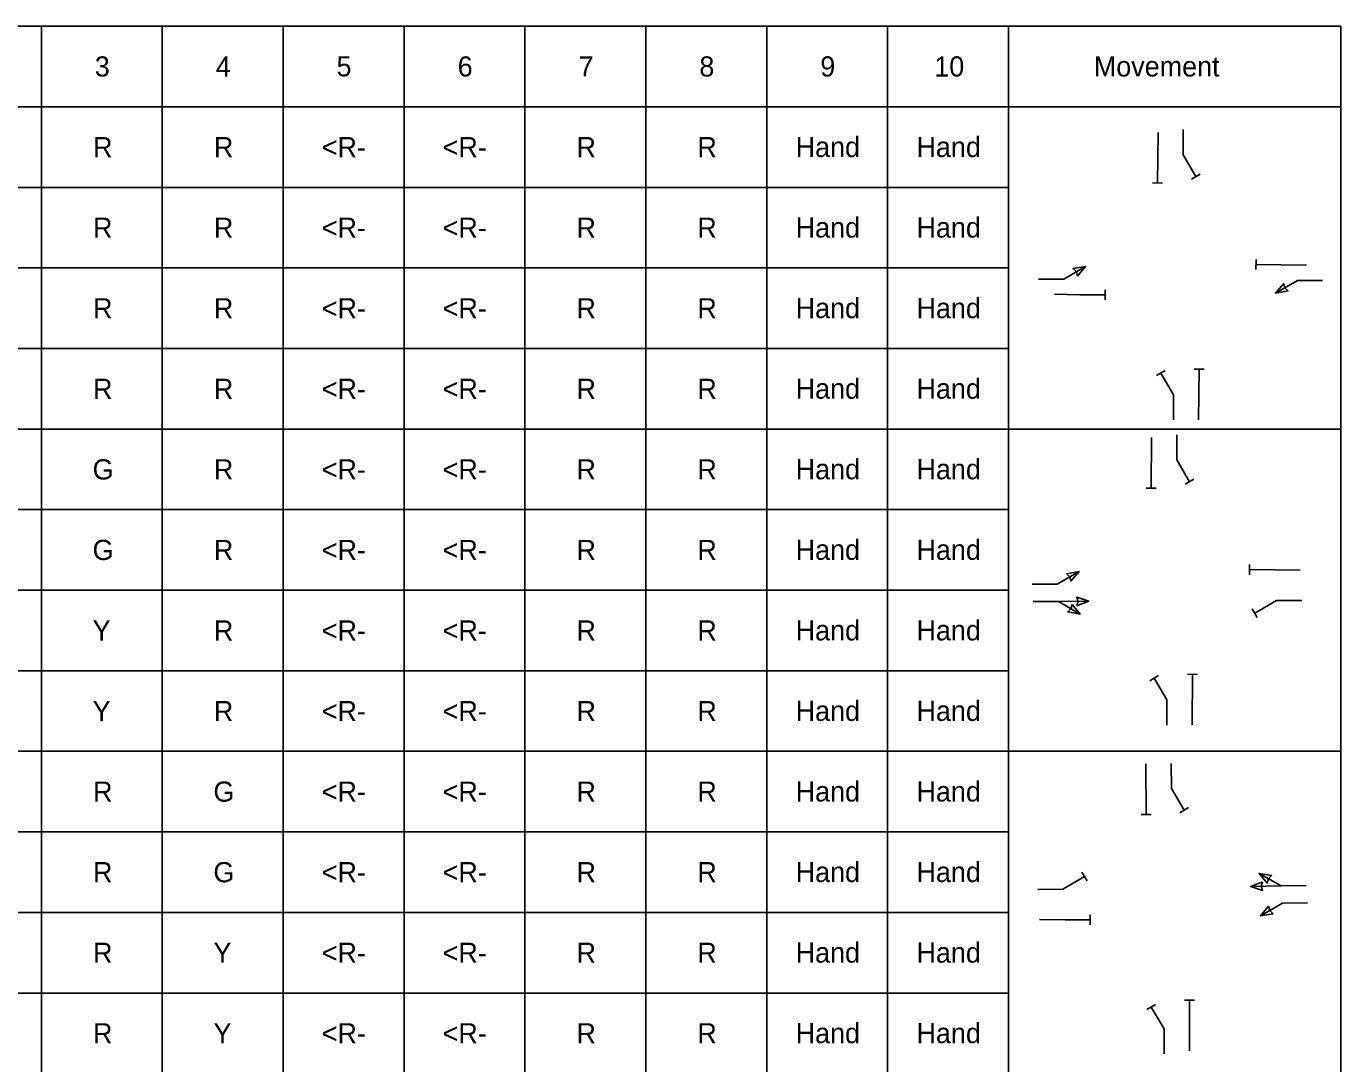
# Model space of a CAD drawing. Extents: x 515543 to 517243, y 660510 to 662861.
# Drawn here: x 515943.9 to 516385.7, y 660844.6 to 661193.4 of the extents above; entities that cross this region are included whole.
import ezdxf

# ---------------------------------------------------------------- set-up
doc = ezdxf.new("R2010")
doc.units = 0
doc.layers.add('Default', color=7, linetype='Continuous')

msp = doc.modelspace()

# ---------------------------------------------------------------- linework, layer by layer
at = {"layer": 'Default'}
for p, q in [((515695.04, 661193.38), (516385.67, 661193.38)), ((515948.98, 661193.38), (515948.98, 660597.54)), ((515989.6, 661193.38), (515989.6, 660597.54)), ((516030.23, 661193.38), (516030.23, 660597.54)), ((516070.85, 661193.38), (516070.85, 660597.54)), ((516111.48, 661193.38), (516111.48, 660597.54)), ((516152.1, 661193.38), (516152.1, 660597.54)), ((516192.73, 661193.38), (516192.73, 660597.54)), ((516233.35, 661193.38), (516233.35, 660597.54)), ((516273.98, 661193.38), (516273.98, 660597.54)), ((516385.67, 661193.38), (516385.67, 660597.54)), ((515695.04, 661166.29), (516385.67, 661166.29)), ((516324.26, 661157.72), (516324.12, 661140.69)), ((516332.77, 661158.65), (516332.77, 661150.18)), ((516332.77, 661150.18), (516337, 661142.85)), ((516322.43, 661140.7), (516325.81, 661140.67)), ((516338.47, 661143.7), (516335.54, 661142.01)), ((515776.29, 661139.21), (516273.98, 661139.21)), ((516357.2, 661114.98), (516357.17, 661111.6)), ((515776.29, 661112.13), (516273.98, 661112.13)), ((515948.98, 661112.13), (516273.98, 661112.13)), ((516292.57, 661108.4), (516299.9, 661112.63)), ((516299.9, 661112.63), (516295.73, 661111.9)), ((516296.82, 661110.86), (516295.73, 661111.9)), ((516297.18, 661109.39), (516296.82, 661110.86)), ((516299.9, 661112.63), (516297.18, 661109.39)), ((516365.65, 661113.22), (516357.18, 661113.29)), ((516374.22, 661113.06), (516365.65, 661113.22)), ((516284.1, 661108.4), (516292.57, 661108.4)), ((516306.48, 661101.36), (516306.51, 661104.74)), ((516371.11, 661107.94), (516363.78, 661103.71)), ((516363.78, 661103.71), (516366.5, 661106.95)), ((516366.5, 661106.95), (516366.86, 661105.48)), ((516366.86, 661105.48), (516367.95, 661104.44)), ((516379.57, 661107.94), (516371.11, 661107.94)), ((516289.45, 661103.28), (516298.03, 661103.12)), ((516298.03, 661103.12), (516306.49, 661103.05)), ((516363.78, 661103.71), (516367.95, 661104.44)), ((515776.29, 661085.04), (516273.98, 661085.04)), ((516339.75, 661078.09), (516336.37, 661078.12)), ((516337.92, 661061.07), (516338.06, 661078.11)), ((516323.71, 661075.96), (516326.64, 661077.66)), ((516329.41, 661069.48), (516325.18, 661076.81)), ((516329.41, 661061.02), (516329.41, 661069.48)), ((515695.04, 661057.96), (516385.67, 661057.96)), ((516192.73, 661057.96), (516233.35, 661057.96)), ((516233.35, 661057.96), (516273.98, 661057.96)), ((516330.59, 661056.06), (516330.59, 661047.6)), ((516322.08, 661055.14), (516321.94, 661038.1)), ((516330.59, 661047.6), (516334.82, 661040.27)), ((516336.29, 661041.11), (516333.35, 661039.42)), ((516320.25, 661038.11), (516323.63, 661038.08)), ((515776.29, 661030.88), (516273.98, 661030.88)), ((516355.02, 661012.4), (516354.99, 661009.01)), ((516290.38, 661005.81), (516297.71, 661010.05)), ((516297.71, 661010.05), (516293.55, 661009.31)), ((516294.64, 661008.27), (516293.55, 661009.31)), ((516294.99, 661006.8), (516294.64, 661008.27)), ((516297.71, 661010.05), (516294.99, 661006.8)), ((516363.47, 661010.64), (516355, 661010.7)), ((516372.04, 661010.48), (516363.47, 661010.64)), ((515776.29, 661003.79), (516273.98, 661003.79)), ((515948.98, 661003.79), (516273.98, 661003.79)), ((516281.92, 661005.81), (516290.38, 661005.81)), ((516282.29, 660999.98), (516290.76, 660999.98)), ((516282.29, 660999.98), (516290.76, 660999.98)), ((516290.76, 660999.98), (516300.96, 661000.09)), ((516290.76, 660999.98), (516298.08, 660995.75)), ((516295.36, 660998.99), (516295.01, 660997.53)), ((516298.08, 660995.75), (516295.36, 660998.99)), ((516300.96, 661000.09), (516296.97, 661001.48)), ((516297.41, 661000.04), (516296.97, 661001.48)), ((516300.96, 661000.09), (516297, 660998.59)), ((516297, 660998.59), (516297.41, 661000.04)), ((516364.09, 661000.34), (516356.76, 660996.1)), ((516372.56, 661000.34), (516364.09, 661000.34)), ((516295.01, 660997.53), (516293.92, 660996.48)), ((516298.08, 660995.75), (516293.92, 660996.48)), ((516357.61, 660994.64), (516355.92, 660997.57)), ((515776.29, 660976.71), (516273.98, 660976.71)), ((516321.53, 660973.38), (516324.46, 660975.07)), ((516327.23, 660966.89), (516323, 660974.22)), ((516337.57, 660975.51), (516334.19, 660975.53)), ((516335.74, 660958.48), (516335.88, 660975.52)), ((516327.23, 660958.43), (516327.23, 660966.89)), ((515695.04, 660949.63), (516385.67, 660949.63)), ((516328.71, 660945.58), (516328.8, 660937.11)), ((516320.2, 660945.44), (516320.24, 660928.4)), ((516328.8, 660937.11), (516333.1, 660929.83)), ((516318.55, 660928.39), (516321.93, 660928.4)), ((516334.56, 660930.69), (516331.65, 660928.97)), ((515776.29, 660922.54), (516263.79, 660922.54)), ((515776.29, 660922.54), (516273.98, 660922.54)), ((516292.29, 660903.29), (516299.57, 660907.59)), ((516298.71, 660909.05), (516300.43, 660906.14)), ((516365.61, 660904.41), (516358.24, 660908.56)), ((516358.24, 660908.56), (516361, 660905.35)), ((516358.24, 660908.56), (516362.42, 660907.87)), ((516361, 660905.35), (516361.34, 660906.82)), ((516361.34, 660906.82), (516362.42, 660907.87)), ((516283.82, 660903.2), (516292.29, 660903.29)), ((516355.41, 660904.2), (516359.35, 660905.74)), ((516365.61, 660904.41), (516355.41, 660904.2)), ((516355.41, 660904.2), (516359.42, 660902.84)), ((516359.35, 660905.74), (516358.96, 660904.28)), ((516358.96, 660904.28), (516359.42, 660902.84)), ((516374.08, 660904.5), (516365.61, 660904.41)), ((516374.08, 660904.5), (516365.61, 660904.41)), ((516366.05, 660898.58), (516358.76, 660894.27)), ((516358.76, 660894.27), (516361.45, 660897.54)), ((516361.45, 660897.54), (516361.82, 660896.08)), ((516374.51, 660898.67), (516366.05, 660898.58)), ((515776.29, 660895.46), (516273.98, 660895.46)), ((515776.29, 660895.46), (516273.98, 660895.46)), ((515948.98, 660895.46), (516273.98, 660895.46)), ((515948.98, 660895.46), (516273.98, 660895.46)), ((516284.44, 660893.06), (516293.02, 660892.99)), ((516293.02, 660892.99), (516301.48, 660893.01)), ((516301.49, 660891.32), (516301.48, 660894.71)), ((516358.76, 660894.27), (516362.92, 660895.05)), ((516361.82, 660896.08), (516362.92, 660895.05)), ((515776.29, 660868.38), (516263.79, 660868.38)), ((515776.29, 660868.38), (516273.98, 660868.38)), ((516320.52, 660862.8), (516323.43, 660864.53)), ((516326.28, 660856.38), (516321.98, 660863.66)), ((516336.53, 660865.97), (516333.14, 660865.96)), ((516334.88, 660848.93), (516334.83, 660865.97)), ((516326.37, 660847.92), (516326.28, 660856.38))]:
    msp.add_line(p, q, dxfattribs=at)
for points in [[(516297.18, 661109.39), (516299.9, 661112.63), (516295.73, 661111.9), (516296.82, 661110.86), (516297.18, 661109.39)], [(516366.5, 661106.95), (516363.78, 661103.71), (516367.95, 661104.44), (516366.86, 661105.48), (516366.5, 661106.95)], [(516294.99, 661006.8), (516297.71, 661010.05), (516293.55, 661009.31), (516294.64, 661008.27), (516294.99, 661006.8)], [(516295.36, 660998.99), (516298.08, 660995.75), (516293.92, 660996.48), (516295.01, 660997.53), (516295.36, 660998.99)], [(516297, 660998.59), (516300.96, 661000.09), (516296.97, 661001.48), (516297.41, 661000.04), (516297, 660998.59)], [(516361, 660905.35), (516358.24, 660908.56), (516362.42, 660907.87), (516361.34, 660906.82), (516361, 660905.35)], [(516359.35, 660905.74), (516355.41, 660904.2), (516359.42, 660902.84), (516358.96, 660904.28), (516359.35, 660905.74)], [(516361.45, 660897.54), (516358.76, 660894.27), (516362.92, 660895.05), (516361.82, 660896.08), (516361.45, 660897.54)]]:
    msp.add_lwpolyline(points, dxfattribs=at)

# ---------------------------------------------------------------- texts
for s, height, p in [('3', 6.77, (515966.91, 661176.49)), ('4', 6.77, (516007.56, 661176.45)), ('5', 6.77, (516048.16, 661176.55)), ('6', 6.77, (516088.88, 661176.49)), ('7', 6.77, (516129.55, 661176.5)), ('8', 6.77, (516170.1, 661176.49)), ('9', 6.77, (516210.75, 661176.49)), ('10', 6.771, (516249.06, 661176.49)), ('Movement', 6.771, (516302.68, 661176.5)), ('R', 6.77, (515966.31, 661149.37)), ('R', 6.77, (516006.93, 661149.37)), ('<R-', 6.771, (516043.19, 661149.37)), ('<R-', 6.771, (516083.82, 661149.37)), ('R', 6.77, (516128.81, 661149.37)), ('R', 6.77, (516169.43, 661149.37)), ('Hand', 6.771, (516202.46, 661149.42)), ('Hand', 6.771, (516243.08, 661149.42)), ('R', 6.77, (515966.31, 661122.28)), ('R', 6.77, (516006.93, 661122.28)), ('<R-', 6.771, (516043.19, 661122.28)), ('<R-', 6.771, (516083.82, 661122.28)), ('R', 6.77, (516128.81, 661122.28)), ('R', 6.77, (516169.43, 661122.28)), ('Hand', 6.771, (516202.46, 661122.34)), ('Hand', 6.771, (516243.08, 661122.34)), ('R', 6.77, (515966.31, 661095.2)), ('R', 6.77, (516006.93, 661095.2)), ('<R-', 6.771, (516043.19, 661095.2)), ('<R-', 6.771, (516083.82, 661095.2)), ('R', 6.77, (516128.81, 661095.2)), ('R', 6.77, (516169.43, 661095.2)), ('Hand', 6.771, (516202.46, 661095.25)), ('Hand', 6.771, (516243.08, 661095.25)), ('R', 6.77, (515966.31, 661068.12)), ('R', 6.77, (516006.93, 661068.12)), ('<R-', 6.771, (516043.19, 661068.12)), ('<R-', 6.771, (516083.82, 661068.12)), ('R', 6.77, (516128.81, 661068.12)), ('R', 6.77, (516169.43, 661068.12)), ('Hand', 6.771, (516202.46, 661068.17)), ('Hand', 6.771, (516243.08, 661068.17)), ('G', 6.77, (515966.16, 661041.03)), ('R', 6.77, (516006.93, 661041.03)), ('<R-', 6.771, (516043.19, 661041.03)), ('<R-', 6.771, (516083.82, 661041.03)), ('R', 6.77, (516128.81, 661041.03)), ('R', 6.77, (516169.43, 661041.03)), ('Hand', 6.771, (516202.46, 661041.09)), ('Hand', 6.771, (516243.08, 661041.09)), ('G', 6.77, (515966.16, 661013.95)), ('R', 6.77, (516006.93, 661013.95)), ('<R-', 6.771, (516043.19, 661013.95)), ('<R-', 6.771, (516083.82, 661013.95)), ('R', 6.77, (516128.81, 661013.95)), ('R', 6.77, (516169.43, 661013.95)), ('Hand', 6.771, (516202.46, 661014)), ('Hand', 6.771, (516243.08, 661014)), ('Y', 6.77, (515966.18, 660986.87)), ('R', 6.77, (516006.93, 660986.87)), ('<R-', 6.771, (516043.19, 660986.87)), ('<R-', 6.771, (516083.82, 660986.87)), ('R', 6.77, (516128.81, 660986.87)), ('R', 6.77, (516169.43, 660986.87)), ('Hand', 6.771, (516202.46, 660986.92)), ('Hand', 6.771, (516243.08, 660986.92)), ('Y', 6.77, (515966.18, 660959.78)), ('R', 6.77, (516006.93, 660959.78)), ('<R-', 6.771, (516043.19, 660959.78)), ('<R-', 6.771, (516083.82, 660959.78)), ('R', 6.77, (516128.81, 660959.78)), ('R', 6.77, (516169.43, 660959.78)), ('Hand', 6.771, (516202.46, 660959.84)), ('Hand', 6.771, (516243.08, 660959.84)), ('R', 6.77, (515966.31, 660932.7)), ('R', 6.77, (515966.31, 660932.7)), ('G', 6.77, (516006.78, 660932.7)), ('<R-', 6.771, (516043.19, 660932.7)), ('<R-', 6.771, (516043.19, 660932.7)), ('<R-', 6.771, (516083.82, 660932.7)), ('<R-', 6.771, (516083.82, 660932.7)), ('R', 6.77, (516128.81, 660932.7)), ('R', 6.77, (516128.81, 660932.7)), ('R', 6.77, (516169.43, 660932.7)), ('R', 6.77, (516169.43, 660932.7)), ('Hand', 6.771, (516202.46, 660932.75)), ('Hand', 6.771, (516202.46, 660932.75)), ('Hand', 6.771, (516243.08, 660932.75)), ('Hand', 6.771, (516243.08, 660932.75)), ('R', 6.77, (515966.31, 660905.62)), ('R', 6.77, (515966.31, 660905.62)), ('G', 6.77, (516006.78, 660905.61)), ('<R-', 6.771, (516043.19, 660905.62)), ('<R-', 6.771, (516043.19, 660905.62)), ('<R-', 6.771, (516083.82, 660905.62)), ('<R-', 6.771, (516083.82, 660905.62)), ('R', 6.77, (516128.81, 660905.62)), ('R', 6.77, (516128.81, 660905.62)), ('R', 6.77, (516169.43, 660905.62)), ('R', 6.77, (516169.43, 660905.62)), ('Hand', 6.771, (516202.46, 660905.67)), ('Hand', 6.771, (516202.46, 660905.67)), ('Hand', 6.771, (516243.08, 660905.67)), ('Hand', 6.771, (516243.08, 660905.67)), ('R', 6.77, (515966.31, 660878.53)), ('R', 6.77, (515966.31, 660878.53)), ('Y', 6.77, (516006.81, 660878.53)), ('<R-', 6.771, (516043.19, 660878.53)), ('<R-', 6.771, (516043.19, 660878.53)), ('<R-', 6.771, (516083.82, 660878.53)), ('<R-', 6.771, (516083.82, 660878.53)), ('R', 6.77, (516128.81, 660878.53)), ('R', 6.77, (516128.81, 660878.53)), ('R', 6.77, (516169.43, 660878.53)), ('R', 6.77, (516169.43, 660878.53)), ('Hand', 6.771, (516202.46, 660878.59)), ('Hand', 6.771, (516243.08, 660878.59)), ('R', 6.77, (515966.31, 660851.45)), ('R', 6.77, (515966.31, 660851.45)), ('Y', 6.77, (516006.81, 660851.45)), ('<R-', 6.771, (516043.19, 660851.45)), ('<R-', 6.771, (516043.19, 660851.45)), ('<R-', 6.771, (516083.82, 660851.45)), ('<R-', 6.771, (516083.82, 660851.45)), ('R', 6.77, (516128.81, 660851.45)), ('R', 6.77, (516128.81, 660851.45)), ('R', 6.77, (516169.43, 660851.45)), ('R', 6.77, (516169.43, 660851.45)), ('Hand', 6.771, (516202.46, 660851.5)), ('Hand', 6.771, (516243.08, 660851.5))]:
    msp.add_text(s, height=height, dxfattribs=at).set_placement(p)

doc.saveas('drawing.dxf')
